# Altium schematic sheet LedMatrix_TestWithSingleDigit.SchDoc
size A4; Organization: Altium Limited; Address1: L3, 12a Rodborough Rd; Address2: Frenchs Forest; Address3: NSW; Address4: Australia 2086
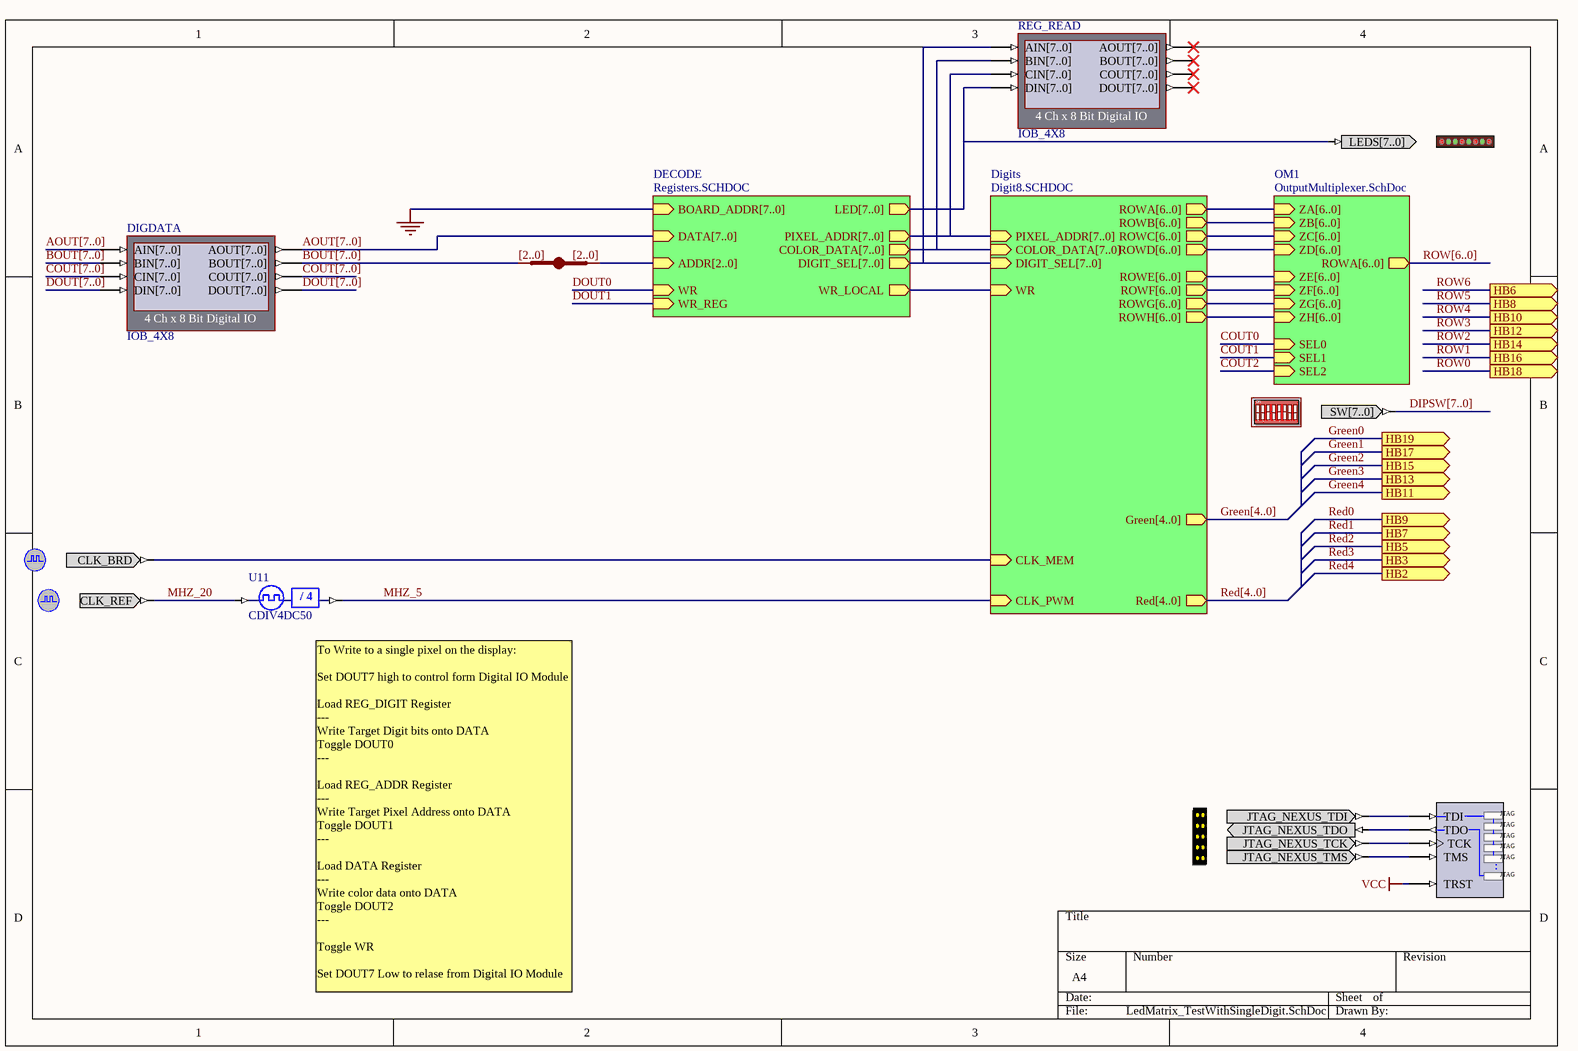
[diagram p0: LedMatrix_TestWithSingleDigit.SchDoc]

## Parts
(Parts that share a designator on the sheet are numbered #1, #2 ... from top to bottom, then left to right.)
?#1  LED  (value not drawn)
?#2  DIPSWITCH  (value not drawn)
?#3  CLOCK_BOARD  (value not drawn)
?#4  CLOCK_REFERENCE  (value not drawn)
?#5  NEXUS_JTAG_CONNECTOR  (value not drawn)
DIGDATA  IOB_4X8
JB_AUTO?  IndexA: [2..0]  (hidden comment: JB)
NEXUS_JTAG_PORT  NEXUS_JTAG_PORT  (value not drawn)
REG_READ  IOB_4X8
U11  CDIV4DC50

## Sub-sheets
DECODE = Registers.SCHDOC: WR (in), ADDR[2..0] (in), BOARD_ADDR[7..0] (in), PIXEL_ADDR[7..0] (out), DATA[7..0] (in), COLOR_DATA[7..0] (out), DIGIT_SEL[7..0] (out), WR_LOCAL (out), LED[7..0] (out), WR_REG (in)
Digits = Digit8.SCHDOC: ROWB[6..0] (out), ROWC[6..0] (out), ROWD[6..0] (out), ROWF[6..0] (out), ROWG[6..0] (out), ROWH[6..0] (out), ROWE[6..0] (out), ROWA[6..0] (out), CLK_MEM (in), CLK_PWM (in), Red[4..0] (out), Green[4..0] (out), PIXEL_ADDR[7..0] (in), COLOR_DATA[7..0] (in), DIGIT_SEL[7..0] (in), WR (in)
OM1 = OutputMultiplexer.SchDoc: ROWA[6..0] (out), SEL0 (in), SEL1 (in), SEL2 (in), ZB[6..0] (in), ZC[6..0] (in), ZD[6..0] (in), ZF[6..0] (in), ZG[6..0] (in), ZH[6..0] (in), ZE[6..0] (in), ZA[6..0] (in)

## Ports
HB2 (out), HB3 (out), HB5 (out), HB6 (out), HB7 (out), HB8 (out), HB9 (out), HB10 (out), HB11 (out), HB12 (out), HB13 (out), HB14 (out), HB15 (out), HB16 (out), HB17 (out), HB18 (out), HB19 (out)

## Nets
VCC: NEXUS_JTAG_PORT.TRST
MHZ_5: U11.CLKDV ; sheet Digits/CLK_PWM
MHZ_20: ?#4.CLK_REF U11.CLKIN
Net?#3_CLK_BRD: ?#3.CLK_BRD ; sheet Digits/CLK_MEM
Net?#5_JTAG_NEXUS_TCK: ?#5.JTAG_NEXUS_TCK NEXUS_JTAG_PORT.TCK
Net?#5_JTAG_NEXUS_TDI: ?#5.JTAG_NEXUS_TDI NEXUS_JTAG_PORT.TDI
Net?#5_JTAG_NEXUS_TDO: ?#5.JTAG_NEXUS_TDO NEXUS_JTAG_PORT.TDO
Net?#5_JTAG_NEXUS_TMS: ?#5.JTAG_NEXUS_TMS NEXUS_JTAG_PORT.TMS
(unnamed): sheet Digits/WR, sheet DECODE/WR_LOCAL

Not connected (* = marked no-connect by the designer): ?#1 LEDS[7..0]; ?#2 SW[7..0]; DIGDATA AIN[7..0] AOUT[7..0] BIN[7..0] BOUT[7..0] CIN[7..0] COUT[7..0] DIN[7..0] DOUT[7..0]; JB_AUTO? A[0..0] B[0..0]; REG_READ AIN[7..0] AOUT[7..0]* BIN[7..0] BOUT[7..0]* CIN[7..0] COUT[7..0]* DIN[7..0] DOUT[7..0]*

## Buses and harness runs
bus AOUT[7..0]
bus AOUT[7..0] = sheet DECODE/DATA[7..0]
bus BOUT[7..0]
bus COUT[7..0]
bus DIPSW[7..0]
bus DOUT[7..0]
bus Green[4..0] = sheet Digits/Green[4..0]
bus Red[4..0] = sheet Digits/Red[4..0]
bus ROW[6..0] = sheet OM1/ROWA[6..0]
bus sheet DECODE/COLOR_DATA[7..0] = sheet Digits/COLOR_DATA[7..0]
bus sheet DECODE/DIGIT_SEL[7..0] = sheet Digits/DIGIT_SEL[7..0]
bus sheet DECODE/PIXEL_ADDR[7..0] = sheet Digits/PIXEL_ADDR[7..0]
bus sheet Digits/ROWA[6..0] = sheet OM1/ZA[6..0]
bus sheet Digits/ROWB[6..0] = sheet OM1/ZB[6..0]
bus sheet Digits/ROWC[6..0] = sheet OM1/ZC[6..0]
bus sheet Digits/ROWD[6..0] = sheet OM1/ZD[6..0]
bus sheet Digits/ROWE[6..0] = sheet OM1/ZE[6..0]
bus sheet Digits/ROWF[6..0] = sheet OM1/ZF[6..0]
bus sheet Digits/ROWG[6..0] = sheet OM1/ZG[6..0]
bus sheet Digits/ROWH[6..0] = sheet OM1/ZH[6..0]

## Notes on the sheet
- (near U11) To Write to a single pixel on the display:
  Set DOUT7 high to control form Digital IO Module
  Load REG_DIGIT Register
  ---
  Write Target Digit bits onto DATA
  Toggle DOUT0
  ---
  Load REG_ADDR Register
  ---
  Write Target Pixel Address onto DATA
  Toggle DOUT1
  ---
  Load DATA Register
  ---
  Write color data onto DATA
  Toggle DOUT2
  ---
  Toggle WR
  Set DOUT7 Low to relase from Digital IO Module
- Labels drawn without touching a wire or pin: GNDBUS[..]

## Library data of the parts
?#1 = LED: 8-Way LEDS; PortComponent: True
?#2 = DIPSWITCH: 8-Way Dip Switch; PortComponent: True
?#3 = CLOCK_BOARD: Global System Clock Supply; PortComponent: True
?#4 = CLOCK_REFERENCE: Global System Clock Reference Supply; PortComponent: True
?#5 = NEXUS_JTAG_CONNECTOR: JTAG Port; PortComponent: True
DIGDATA REG_READ = IOB_4X8: 4 Ch x 8 Bit Digital IO; NEXUS_CORE: Instrument; NEXUS_JTAG_DEVICE: True; NEXUS_JTAG_ORDER: 0
JB_AUTO? = JB: System BUS Joiner; ArchiveName: GENERIC
NEXUS_JTAG_PORT = NEXUS_JTAG_PORT: Soft Nexus-Chain Connector; NEXUS_JTAG_CONNECTOR: True
U11 = CDIV4DC50: Clock Divider by 4 with 50% Duty Cycle Output; ArchiveName: GENERIC; Xilinx Equivalent: CLK_DIV4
